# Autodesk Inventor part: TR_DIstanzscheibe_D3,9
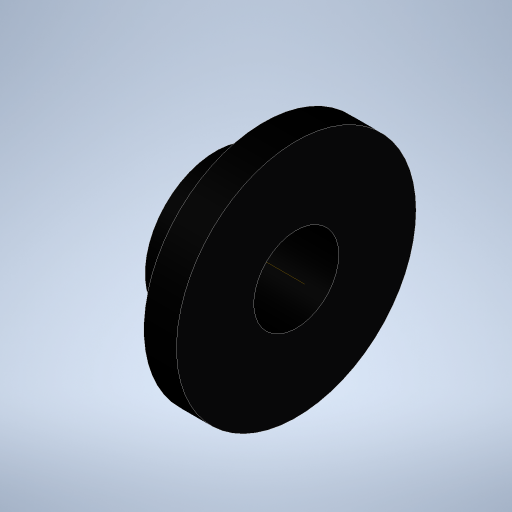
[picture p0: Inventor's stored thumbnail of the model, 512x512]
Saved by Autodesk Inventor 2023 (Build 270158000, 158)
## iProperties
Created: 2023-11
Part Number: TR_DIstanzscheibe_D3,9
Material: PC/ABS-Kunststoff
Document SubType Name: Modeling
Designer: Admin
Density: 0.357273 g/cm^3
Appearance: Glatt - Schwarz
Author: Admin
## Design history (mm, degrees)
sketch "Skizze1"
  geometry: L1 (0, -1.95)-(3.7, -1.95); L2 (3.7, -1.95)-(3.7, -3.25); L3 (3.7, -3.25)-(1.9, -3.25); L4 (1.9, -3.25)-(1.5, -5.5); L5 (1.5, -5.5)-(0, -5.5); L6 (0, -5.5)-(0, -1.95); L7 (4.44, 0)-(-0.74, 0) reference; 1 further point
  constraints: 12 end point, 3 perpendicular, 1 horizontal, 1 parallel, 1 vertical alignment
  dimensions: "d0" = 1.5 distance of L4.end L5.end; "d1" = 5.5 vertical distance of point (0, 0) L4.end; "d2" = 3.25 vertical distance of point (0, 0) L2.end; "d3" = 1.95 vertical distance of point (0, 0) L1.end; "d4" = 3.7 horizontal distance of point (0, 0) L1.end; "d5" = 1.9 horizontal distance of point (0, 0) L3.end
revolve "Umdrehung1" sketch "Skizze1" stored, may be unused: angle "d6" = 90 deg
node "Volumenkörper1"
